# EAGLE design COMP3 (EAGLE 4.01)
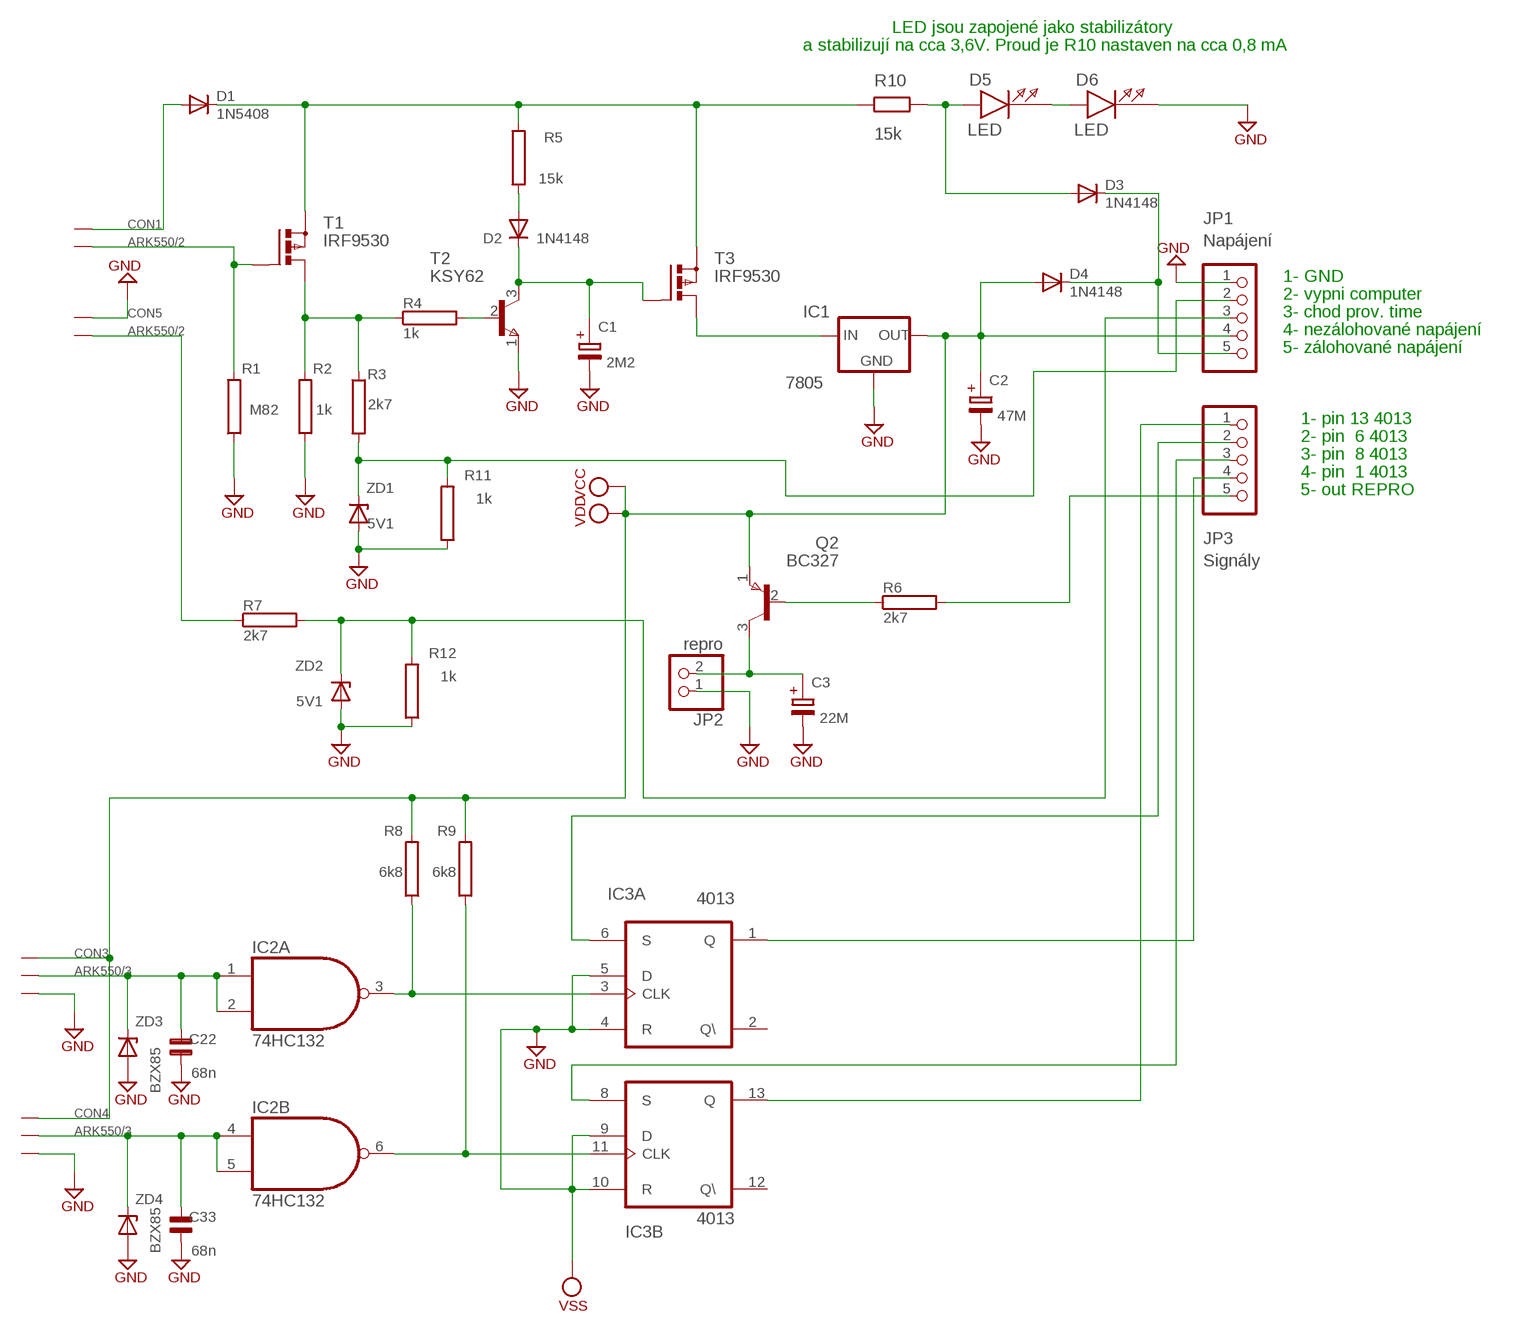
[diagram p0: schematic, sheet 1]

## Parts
C1  2M2  ETR1  [ETR1]
C2  47M  ETR1  [ETR1]
C3  22M  ETR1  [ETR1]
C22  68n  C5B2,5  [C5B2,5]
C33  68n  C5B2,5  [C5B2,5]
CON1  ARK550/2  [ARK550/2]
CON3  ARK550/3  [ARK550/3]
CON4  ARK550/3  [ARK550/3]
CON5  ARK550/2  [ARK550/2]
D1  1N5408  1N5400  [DO201-15]
D2  1N4148  [DO35-10]
D3  1N4148  [DO35-10]
D4  1N4148  [DO35-10]
D5  LED  LED3MMZELE  [LED3]
D6  LED  LED3MMZELE  [LED3]
IC1  7805  78XXS  [78XXS]
IC2  74HC132  7400  [DIL14]
IC3  4013  [DIL14]
JP1  Napájení  PINHD-1X5  [1X05]
JP2  repro  PINHD-1X2  [1X02]
JP3  Signály  PINHD-1X5  [1X05]
Q2  BC327  [TO92]
R1  M82  0204/5  [0204/5]
R2  1k  0204/5  [0204/5]
R3  2k7  0204/5  [0204/5]
R4  1k  0204/5  [0204/5]
R5  15k  0204/5  [0204/5]
R6  2k7  0204/5  [0204/5]
R7  2k7  0204/5  [0204/5]
R8  6k8  0204/5  [0204/5]
R9  6k8  0204/5  [0204/5]
R10  15k  RR  [RR]
R11  1k  0204/5  [0204/5]
R12  1k  0204/5  [0204/5]
T1  IRF9530  [TO220BV]
T2  KSY62  BC237  [TO92]
T3  IRF9530  [TO220BV]
ZD1  5V1  BZX85  [DO41Z10]
ZD2  5V1  BZX85  [DO41Z10]
ZD3  BZX85  [DO41Z10]
ZD4  BZX85  [DO41Z10]

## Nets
GND: C1.- C2.- C3.- C22.1 C33.1 CON3.3 CON4.3 CON5.1 D6.K IC1.GND IC3.4(A:R) IC3.5(A:D) IC3.9(B:D) IC3.10(B:R) JP1.1 JP2.1 R1.1 R2.1 R11.1 R12.1 T2.1(E) ZD1.A ZD2.A ZD3.A ZD4.A ; supply symbol labelled VSS
N$1: CON1.2 R1.2 T1.G
N$2: JP1.2 R3.2 R11.2 ZD1.K
N$3: R4.2 T2.2(B)
N$4: R2.2 R3.1 R4.1 T1.D
N$5: D2.A R5.1
N$6: D1.K R5.2 R10.1 T1.S T3.S
N$7: C1.+ D2.K T2.3(C) T3.G
N$9: CON1.1 D1.A
N$10: IC1.IN T3.D
N$11: D3.K D4.K JP1.5
N$12: Q2.2(B) R6.1
N$13: D3.A D5.A R10.2
N$15: JP3.5 R6.2
N$16: D5.K D6.A
N$18: C3.+ JP2.2 Q2.3(C)
N$20: CON5.2 R7.1
N$21: JP1.3 R7.2 R12.2 ZD2.K
N$24: C22.2 CON3.2 IC2.1(A:I0) IC2.2(A:I1) ZD3.K
N$25: C33.2 CON4.2 IC2.4(B:I0) IC2.5(B:I1) ZD4.K
N$26: IC2.3(A:O) IC3.3(A:CLK) R8.1
N$27: IC2.6(B:O) IC3.11(B:CLK) R9.1
N$43: IC3.1(A:Q) JP3.4
N$44: IC3.13(B:Q) JP3.1
N$45: IC3.6(A:S) JP3.2
N$46: IC3.8(B:S) JP3.3
VDD: C2.+ CON3.1 CON4.1 D4.A IC1.OUT JP1.4 Q2.1(E) R8.2 R9.2 ; supply symbol labelled VCC
Unconnected: IC2.8(C:O) IC2.9(C:I0) IC2.10(C:I1) IC2.11(D:O) IC2.12(D:I0) IC2.13(D:I1) IC3.2(A:Q\) IC3.12(B:Q\)

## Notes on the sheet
- LED jsou zapojené jako stabilizátory
- a stabilizují na cca 3,6V. Proud je R10 nastaven na cca 0,8 mA
- 1- GND
- 2- vypni computer
- 3- chod prov. time
- 4- nezálohované napájení
- 5- zálohované napájení
- 1- pin 13 4013
- 2- pin  6 4013
- 3- pin  8 4013
- 4- pin  1 4013
- 5- out REPRO

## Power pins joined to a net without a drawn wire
GND: IC2.7(P:GND) IC3.7(P:VSS)
VDD: IC2.14(P:VCC) IC3.14(P:VDD)

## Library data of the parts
C1-C3 = CAP-TANT:ETR1
C22 C33 = CAP:C5B2,5
CON1 CON5 = GM99:ARK550/2
CON3 CON4 = GM99:ARK550/3
D1 = DIODE:1N5400
D2-D4 = DIODE:1N4148
D5 D6 = GM99:LED3MMZELE
IC1 = V-REG:78XXS
IC2 = 74XX:7400
IC3 = 40XX:4013
JP1 JP3 = PINHEADb:PINHD-1X5
JP2 = PINHEAD:PINHD-1X2
Q2 = PNP:BC327
R1-R9 R11 R12 = R:0204/5
R10 = GM99:RR
T1 T3 = :IRF9530: N-CHANNEL MOS FET
T2 = NPN:BC237
ZD1-ZD4 = DIODE:BZX85

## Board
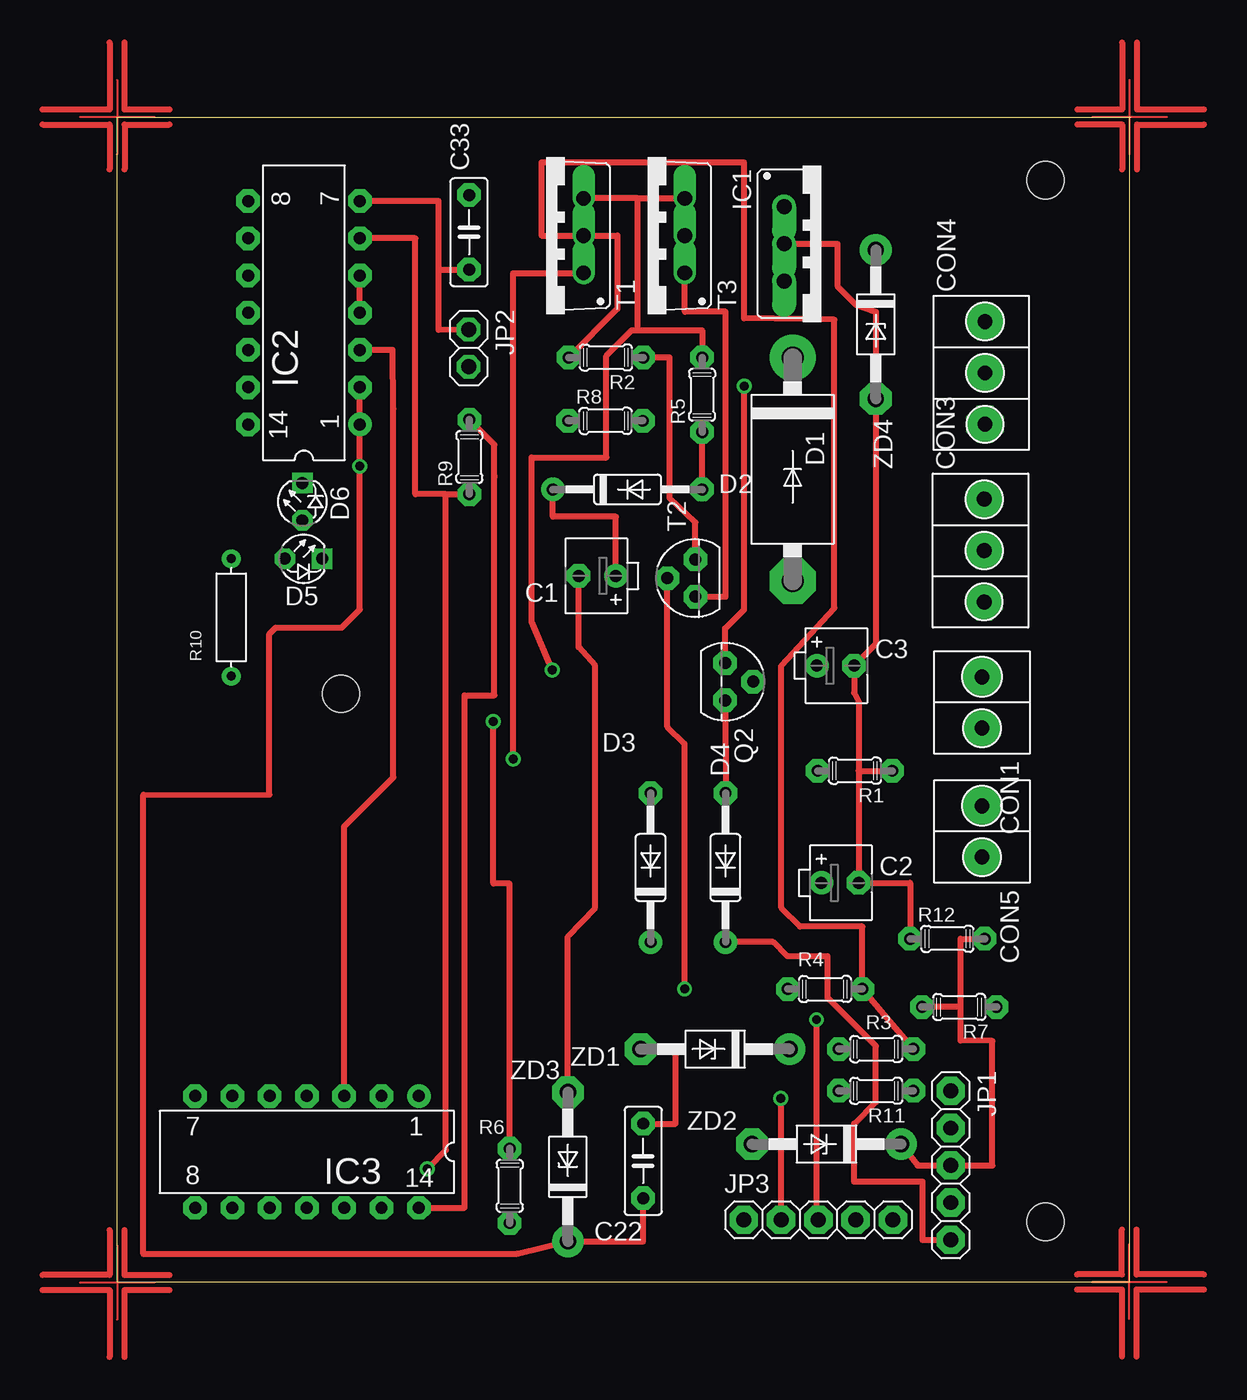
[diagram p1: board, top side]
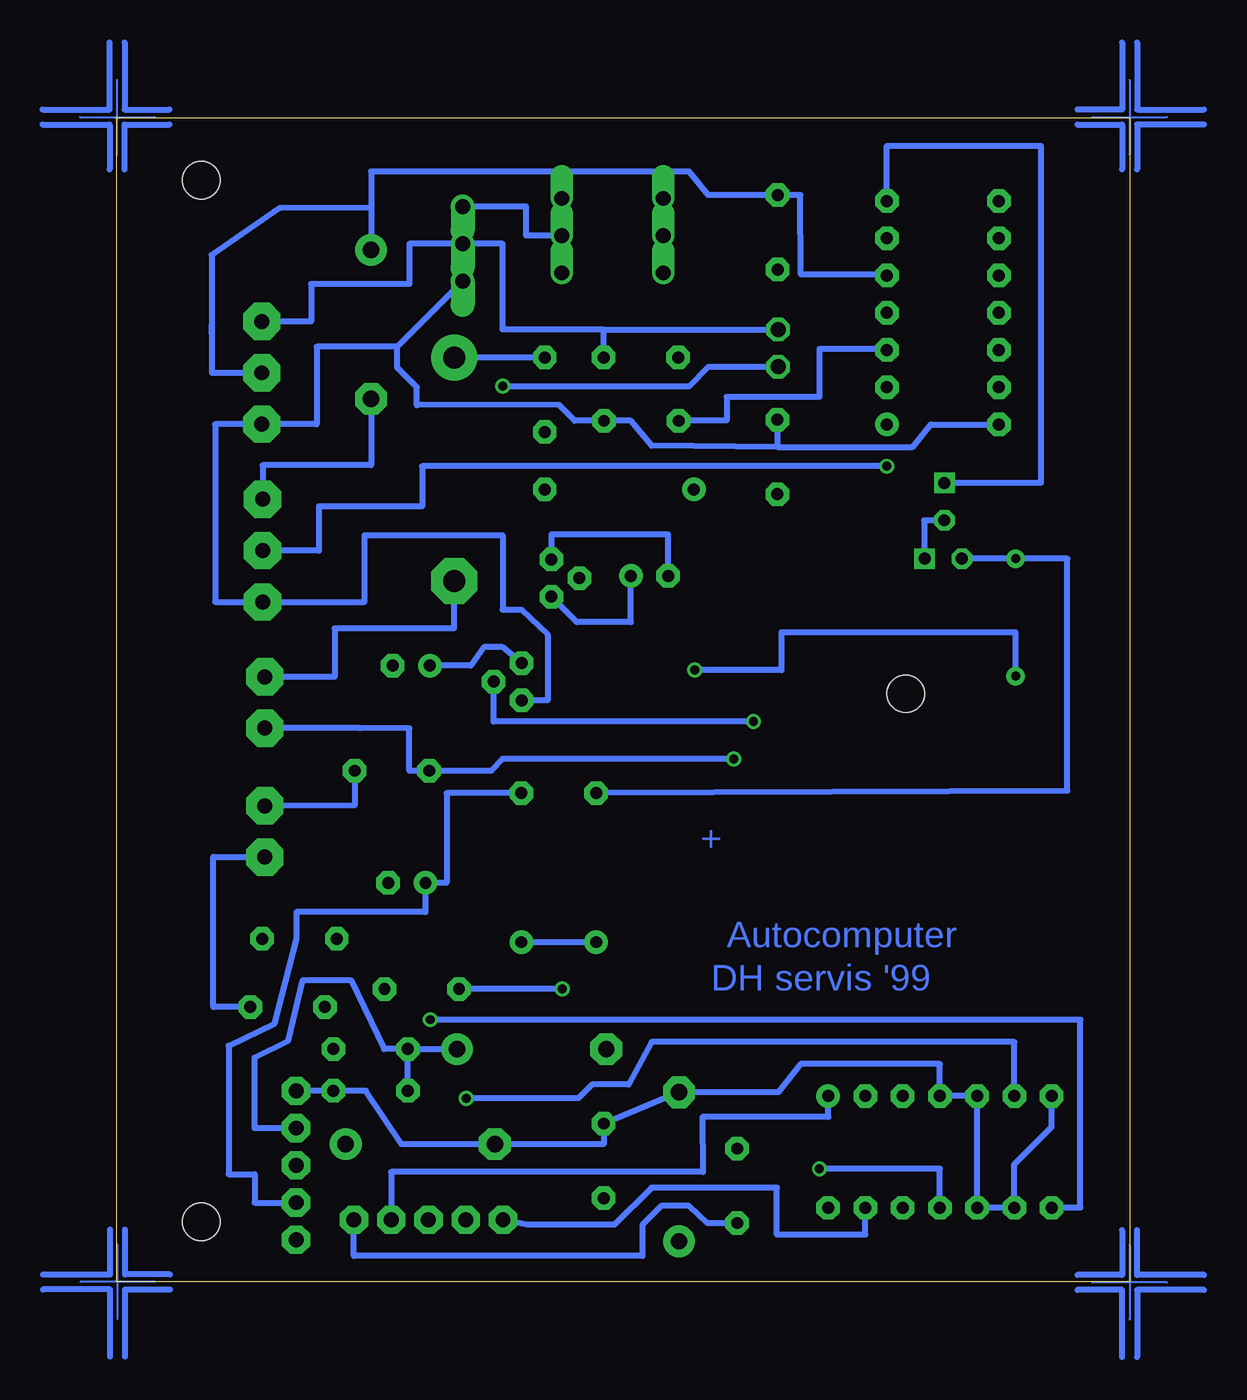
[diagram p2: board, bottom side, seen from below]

Size 69.11 x 79.4 mm. Coordinates in mm from the lower left corner, seen from the top.
Outline: 69.11,79.35 0,79.35 0,0 69.04,0 69.04,79.4
Copper layers used: Top, Bottom
Holes 2.54 mm at 63.28,75.08 63.28,4.08 15.28,40.08

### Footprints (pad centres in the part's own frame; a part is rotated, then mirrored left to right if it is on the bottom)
ETR1 = drill 0.813 pad 1.6 round: + -1.27,0 | drill 0.813 pad 1.6 octagon: - 1.27,0
C5B2,5 = drill 0.813 pad 1.6 octagon: 1 -2.54,0; 2 2.54,0
ARK550/2 = drill 1.016 pad 2.54 octagon: 1 0,0; 2 3.5,0
ARK550/3 = drill 1.016 pad 2.54 octagon: 1 0,0; 2 3.5,0; 3 7,0
DO201-15 = drill 1.499 pad 3.15 octagon: A 7.62,0 | drill 1.499 pad 3.15 round: K -7.62,0
DO35-10 = drill 0.813 pad 1.6 octagon: A 5.08,0 | drill 0.813 pad 1.6 round: K -5.08,0
LED3 = drill 0.813 pad 1.397 octagon: A -1.27,0 | drill 0.813 pad 1.397 square: K 1.27,0
78XXS = drill 1.016 pad 1.626 offset: GND 0,-2.54; IN -2.54,-2.54; OUT 2.54,-2.54
DIL14 = drill 0.813 pad 1.6 round: 1 -7.62,-3.81 | drill 0.813 pad 1.6 octagon: 2 -5.08,-3.81; 3 -2.54,-3.81; 4 0,-3.81; 5 2.54,-3.81; 6 5.08,-3.81; 7 7.62,-3.81; 8 7.62,3.81; 9 5.08,3.81; 10 2.54,3.81; 11 0,3.81; 12 -2.54,3.81; 13 -5.08,3.81; 14 -7.62,3.81
1X05 = drill 1.016 pad 1.93 octagon: 1 -5.08,0; 2 -2.54,0; 3 0,0; 4 2.54,0; 5 5.08,0
1X02 = drill 1.016 pad 1.6 octagon: 1 -1.27,0; 2 1.27,0
TO92 = drill 0.813 pad 1.6 octagon: 1 1.27,0; 2 0,1.905; 3 -1.27,0
0204/5 = drill 0.813 pad 1.6 octagon: 1 -2.54,0; 2 2.54,0
RR = drill 0.61 pad 1.27 round: 1 0,0; 2 8,0
TO220BV = drill 1.016 offset: D 0,-2.54; G -2.54,-2.54; S 2.54,-2.54
DO41Z10 = drill 1.118 pad 2.159 octagon: A 5.08,0 | drill 1.118 pad 2.159 round: K -5.08,0

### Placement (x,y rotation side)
C1  32.74,48.11 180 top
C2  49.28,27.18 0 top
C3  48.97,41.99 0 top
C22  35.86,8.23 270 top
C33  24,71.53 90 top
CON1  58.95,41.22 270 top
CON3  59.11,46.33 90 top
CON4  59.16,58.45 90 top
CON5  58.95,32.44 270 top
D1  46.05,55.37 270 top
D2  34.8,54 0 top
D3  36.37,28.22 90 top
D4  41.48,28.22 90 top
D5  12.73,49.28 0 top
D6  12.65,53.16 90 top
IC1  48.01,70.74 270 top
IC2  12.75,66.04 90 top
IC3  12.95,8.84 180 top
JP1  56.82,7.92 270 top
JP2  23.98,63.63 270 top
JP3  47.8,4.22 0 top
Q2  41.45,40.89 270 top
R1  50.29,34.82 180 top
R2  33.32,62.99 180 top
R3  51.74,15.85 180 top
R4  48.26,19.94 180 top
R5  39.88,60.45 90 top
R6  26.77,6.53 270 top
R7  57.4,18.72 180 top
R8  33.3,58.67 0 top
R9  24.03,56.21 90 top
R10  7.8,41.27 90 top
R11  51.74,13 180 top
R12  56.59,23.37 0 top
T1  29.26,71.3 90 top
T2  39.42,47.96 90 top
T3  36.17,71.3 90 top
U$21  [ROH]  0.03,79.38 270 top
U$22  [ROH]  0.03,-0.05 0 top
U$23  [ROH]  68.99,-0.03 90 top
U$24  [ROH]  69.01,79.38 180 top
ZD1  40.77,15.85 180 top
ZD2  48.36,9.37 180 top
ZD3  30.73,7.82 90 top
ZD4  51.71,65.25 270 top

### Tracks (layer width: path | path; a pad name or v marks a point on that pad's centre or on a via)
GND
  Top 0.406: IC1.GND 49.1,70.74 49.1,67.87 50.37,66.6 51.71,66.12 ZD4.A 51.71,54.86 | 21.92,68.99 21.92,64.87 JP2.1 | 21.92,68.99 21.92,73.66 IC2.7 | T2.1 39.42,51.77 37.67,53.42 37.67,62.99 R2.1 | C22.1 38.07,10.77 38.07,15.85 ZD1.A | 50.55,34.82 C2.- 54.05,27.18 R12.1 54.05,23.34 | 50.55,34.82 R1.1 | 51.71,54.86 51.71,43.46 C3.- 50.24,40.13 50.55,39.55 50.55,34.82 | 21.92,68.99 C33.1 | 51.71,54.86 | ZD3.A 30.73,23.52 32.59,25.48 32.59,41.99 31.47,43.26 C1.-
  Bottom 0.406: T2.1 39.42,50.93 31.47,50.93 C1.- 31.47,48.08 | R2.1 35.86,64.9 | 35.86,64.9 JP2.1 | 35.86,64.9 42.75,64.9 42.75,70.74 IC1.GND 49.1,70.74 49.1,68 55.8,68 55.8,65.45 CON4.3 | ZD4.A 51.71,55.65 59.11,55.65 CON3.3 | 52.83,32.46 | R1.1 52.83,32.46 | 52.83,32.46 CON5.1 | JP1.1 R11.1 52.07,13.01 49.63,9.37 ZD2.A 35.86,9.37 C22.1 ZD3.A 23.95,12.9 22.43,14.83 12.95,14.83 IC3.4 IC3.5 IC3.10 IC3.9 7.87,8 5.33,10.54 IC3.7 | D6.K 6.07,54.43 6.07,77.42 16.56,77.42 IC2.7
N$1  (via drill 0.61 pad 1.02)
  Top 0.406: v27,35.61 27,68.73 T1.G
  Bottom 0.406: v27,35.61 42.75,35.64 43.51,34.82 R1.2 | R1.2 47.78,34.82 | R1.2 49.1,34.82 49.1,37.72 52.48,37.72 CON1.2
N$2
  Bottom 0.406: R3.2 ZD1.K | R3.2 50.83,15.85 53.06,20.52 56.39,20.52 57.4,16.38 59.66,15.27 59.66,10.47 JP1.2 | R11.2 R3.2
N$3  (via drill 0.61 pad 1.02)
  Top 0.406: T2.2 37.52,37.82 38.68,36.65 v38.68,19.96
  Bottom 0.406: v38.68,19.96 44.4,19.96 R4.2
N$4
  Top 0.406: R3.1 52.63,17.75 R4.1 50.8,24.21 46.56,24.21 45.29,25.48 45.29,41.99 48.9,45.92 48.9,65.56 42.75,65.66 42.75,76.28 28.93,76.28 28.93,71.3 T1.D 34.11,71.3 34.11,66.32 R2.2
N$5
  Top 0.406: D2.A R5.1
N$6  (via drill 0.61 pad 1.02)
  Top 0.406: R5.2 39.88,64.85 35.48,64.85 | 35.48,64.85 35.48,73.84 | 35.48,73.84 T3.S | 35.48,73.84 T1.S | 35.48,64.85 35.08,64.85 33.35,63.12 33.35,56.19 28.27,56.19 28.27,44.98 v29.67,41.68
  Bottom 0.406: R5.2 D1.K | R10.1 7.8,44.25 23.75,44.25 23.75,41.68 v29.67,41.68
N$7
  Top 0.406: C1.+ 34.01,52.15 29.72,52.15 D2.K | T2.3 41.48,46.69 41.48,66.12 38.71,66.12 T3.G
  Bottom 0.406: T2.3 37.69,44.96 34.01,44.96 C1.+
N$9
  Bottom 0.406: D1.A 46.05,44.53 54.2,44.53 54.2,41.22 | 54.2,41.22 | 54.2,41.22 CON1.1
N$10
  Bottom 0.406: T3.D 41.15,71.3 41.15,73.28 IC1.IN
N$11
  Top 0.406: D4.K 44.73,23.14 45.69,22.17 48.44,22.17 48.44,19.33 51.71,16.05 51.71,12.24 50.24,10.77 50.24,6.83 54.89,6.83 54.89,3.02 54.89,2.85 JP1.5
  Bottom 0.406: D4.K D3.K
N$12  (via drill 0.61 pad 1.02)
  Top 0.406: v25.65,38.18 25.65,27.13 26.77,27.13 R6.1
  Bottom 0.406: v25.65,38.18 43.36,38.18 Q2.2
N$13
  Bottom 0.406: D3.A 4.27,33.45 4.27,49.28 R10.2 D5.A
N$14  (via drill 0.61 pad 1.02)
  other vias: 29.67,41.71
N$15
  Bottom 0.406: R6.2 28.78,3.99 30.05,5.16 31.95,5.16 33.22,3.89 33.22,1.75 52.88,1.75 JP3.5
N$16
  Bottom 0.406: 14.02,49.28 14.02,49.25 | 14.02,49.28 D5.K | D6.A 14.02,51.89 14.02,49.28
N$18  (via drill 0.61 pad 1.02)
  Top 0.406: v42.75,61.04 42.75,45.8 41.45,44.53 Q2.3
  Bottom 0.406: 47.83,41.99 C3.+ 44.93,41.99 44.02,43.26 42.75,43.26 Q2.3 | JP2.2 28.73,62.36 30.05,61.04 v42.75,61.04
N$20
  Bottom 0.406: R7.1 62.46,18.72 62.46,28.96 61.19,28.94 CON5.2
N$21
  Top 0.406: R7.2 57.51,18.72 57.51,18.69 | 57.51,18.69 57.51,16.43 59.66,16.41 59.66,7.93 JP1.3 54.56,7.93 ZD2.K | R12.2 57.51,23.37 57.51,18.69
N$24  (via drill 0.61 pad 1.02)
  Top 0.406: C22.2 35.86,2.74 ZD3.K 27.25,1.91 16.74,1.88 1.8,1.88 1.8,33.17 10.39,33.2 10.39,44.15 10.82,44.58 15.32,44.58 16.56,45.82 v16.56,55.58 IC2.1 | IC2.1 16.59,58.39 | IC2.1 IC2.2
  Bottom 0.406: v16.56,55.58 48.23,55.58 48.23,52.83 55.27,52.83 55.27,49.83 CON3.2
N$25
  Top 0.406: IC2.4 IC2.5
  Bottom 0.406: IC2.5 17.35,68.66 22.43,68.66 22.45,74.07 C33.2 28.75,74.07 30.05,75.67 51.71,75.67 51.71,73.18 | 51.71,73.18 ZD4.K | 62.56,64.59 62.59,69.98 57.89,73.2 51.71,73.18 | 62.56,64.59 62.56,65.25 | CON4.2 62.56,61.95 62.56,64.59
N$26
  Top 0.406: IC3.3 15.49,30.76 15.49,31.01 18.85,34.37 18.85,59.49 18.8,63.5 IC2.3
  Bottom 0.406: R8.1 30.02,58.7 27.48,58.7 27.48,60.3 21.16,60.3 21.16,63.58 17.35,63.58 IC2.3
N$27  (via drill 0.61 pad 1.02)
  Top 0.406: 22.43,53.67 20.35,53.67 20.35,71.12 IC2.6 16.54,71.12 | 22.43,53.67 R9.1 | v21.16,7.7 22.43,8.97 22.43,53.67
  Bottom 0.406: IC3.11 12.95,7.7 v21.16,7.7
N$43
  Bottom 0.406: IC3.1 20.55,11.23 29.13,11.23 29.11,7.47 50.34,7.47 JP3.4
N$44
  Bottom 0.406: JP3.1 41.07,3.89 35.13,3.89 32.59,6.4 24.05,6.4 24.05,3.2 18.03,3.2 IC3.13
N$45  (via drill 0.61 pad 1.02)
  Top 0.406: JP3.2 45.26,4.19 45.24,4.19 v45.24,12.5
  Bottom 0.406: IC3.6 7.87,16.33 32.59,16.33 34.16,13.44 36.65,13.44 37.59,12.5 v45.24,12.5
N$46  (via drill 0.61 pad 1.02)
  Top 0.406: v47.68,17.86 47.68,4.22 JP3.3
  Bottom 0.406: IC3.8 3.38,5.03 3.38,17.86 v47.68,17.86
VDD
  Top 0.406: Q2.1 D4.A | IC3.14 23.7,5.03 23.7,39.95 25.73,39.95 25.73,54.84 | 25.73,54.84 25.73,54.92 | R9.2 25.73,57.05 25.73,54.84
  Bottom 0.406: 24.03,56.9 32.59,56.97 34.01,58.67 R8.2 | IC2.14 13.56,58.42 14.81,56.9 24.03,56.9 | R8.2 35.86,58.67 | R8.2 37.85,58.67 38.94,59.77 48.59,59.74 48.59,60.96 49.94,62.31 49.94,63.73 | D4.A 46.56,33.3 46.56,27.18 C2.+ 48.01,25.2 56.79,25.2 56.79,23.37 58.32,17.55 61.42,16.08 61.42,7.32 59.64,7.32 59.64,5.39 JP1.4 | Q2.1 39.67,39.62 39.67,44.12 41.48,45.8 42.75,45.8 42.75,50.88 52.15,50.88 52.15,46.33 CON3.1 62.33,46.33 62.33,58.45 CON4.1 55.42,58.45 55.42,63.73 49.94,63.73 | 49.94,63.73 IC1.OUT | R9.2 24.03,56.9

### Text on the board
Bottom: + | Autocomputer | DH servis '99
